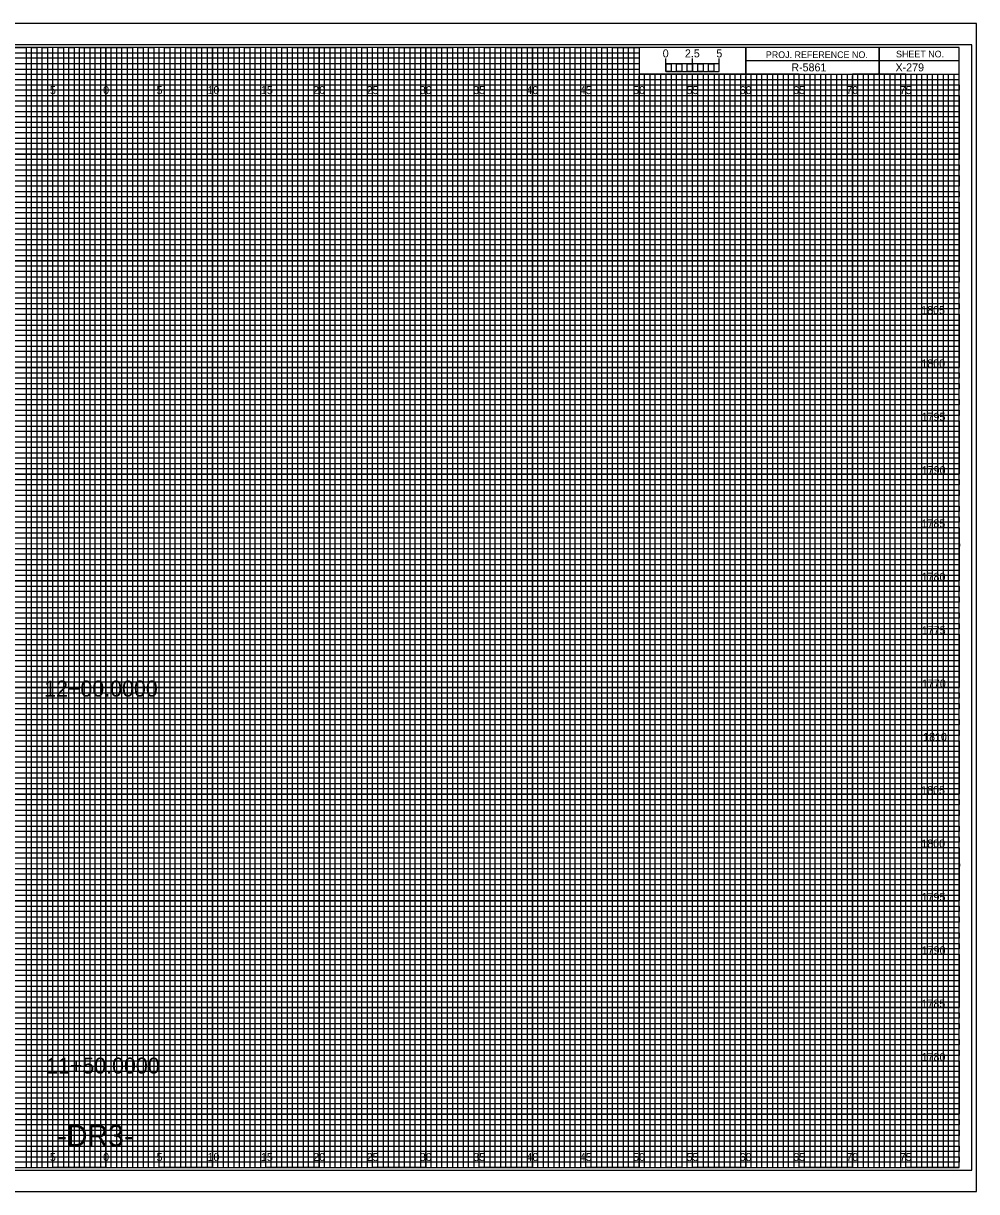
# Model space of a CAD drawing. Extents: x -7 to 162, y -2 to 217.
# Drawn here: x 72.2 to 161.7, y 107.7 to 217.2 of the extents above; entities that cross this region are included whole.
import ezdxf

# ---------------------------------------------------------------- set-up
doc = ezdxf.new("R2010")
doc.units = 0
for name, color, linetype in [('Prop Horizontal Alignment', 7, 'Continuous'), ('Prop XS Alignment Label', 7, 'Continuous'), ('Prop XS Bar Scale Labels', 7, 'Continuous'), ('Prop XS Project Number', 7, 'Continuous'), ('Prop XS Sheet Number', 7, 'Continuous'), ('Raster_Level_0', 7, 'Continuous'), ('Scratch_Level_3', 7, 'Continuous'), ('Sheet Cross Section CELL', 7, 'Continuous'), ('Sheet Cross Section Grid Major CELL', 7, 'Continuous'), ('Sheet Cross Section Grid Middle CELL', 7, 'Continuous'), ('Sheet Cross Section Grid Minor 1 CELL', 7, 'Continuous'), ('Sheet Cross Section Grid Minor 2 CELL', 7, 'Continuous'), ('Sheet Cross Section Scale CELL', 7, 'Continuous'), ('Sheet Cutting Line CELL', 7, 'Continuous'), ('Sheet DOT Grid CELL', 7, 'Continuous'), ('Sheet Plot Border Inside CELL', 7, 'Continuous'), ('Sheet Plot Border Outside CELL', 7, 'Continuous')]:
    doc.layers.add(name, color=color, linetype=linetype)

msp = doc.modelspace()

# ---------------------------------------------------------------- linework, layer by layer
at = {"layer": 'Sheet Cross Section CELL'}
for p, q in [((152.5, 215), (152.5, 212.5)), ((152.5, 212.5), (152.5, 215)), ((160, 213.75), (140, 213.75)), ((140, 213.75), (140, 212.5)), ((140, 212.5), (160, 212.5))]:
    msp.add_line(p, q, dxfattribs=at)
for points in [[(160, 215), (0, 215), (0, 110), (160, 110)], [(140, 215), (130, 215), (130, 212.52), (140, 212.52)], [(160, 215), (140, 215), (140, 212.5), (160, 212.5)]]:
    msp.add_lwpolyline(points, close=True, dxfattribs=at)
at = {"layer": 'Sheet Cross Section Grid Major CELL'}
for p, q in [((75, 215), (70, 215)), ((75, 110), (75, 215)), ((85, 215), (80, 215)), ((80, 215), (80, 110)), ((85, 110), (85, 215)), ((95, 215), (90, 215)), ((90, 215), (90, 110)), ((95, 110), (95, 215)), ((105, 215), (100, 215)), ((100, 215), (100, 110)), ((105, 110), (105, 215)), ((115, 215), (110, 215)), ((110, 215), (110, 110)), ((115, 110), (115, 215)), ((125, 215), (120, 215)), ((120, 215), (120, 110)), ((125, 110), (125, 215)), ((130, 215), (130, 110)), ((135, 110), (135, 212.5)), ((145, 212.5), (140, 212.5)), ((140, 212.5), (140, 110)), ((145, 110), (145, 212.5)), ((155, 212.5), (150, 212.5)), ((150, 212.5), (150, 110)), ((155, 110), (155, 212.5)), ((80, 110), (75, 110)), ((90, 110), (85, 110)), ((100, 110), (95, 110)), ((110, 110), (105, 110)), ((120, 110), (115, 110)), ((130, 110), (125, 110)), ((140, 110), (135, 110)), ((150, 110), (145, 110)), ((160, 110), (155, 110)), ((160, 110), (160, 110))]:
    msp.add_line(p, q, dxfattribs=at)
for points in [[(0, 210), (160, 210), (160, 205), (0, 205)], [(0, 200), (160, 200), (160, 195), (0, 195)], [(0, 190), (160, 190), (160, 185), (0, 185)], [(0, 180), (160, 180), (160, 175), (0, 175)], [(0, 170), (160, 170), (160, 165), (0, 165)], [(0, 160), (160, 160), (160, 155), (0, 155)], [(0, 150), (160, 150), (160, 145), (0, 145)], [(0, 140), (160, 140), (160, 135), (0, 135)], [(0, 130), (160, 130), (160, 125), (0, 125)], [(0, 120), (160, 120), (160, 115), (0, 115)]]:
    msp.add_lwpolyline(points, dxfattribs=at)
at = {"layer": 'Sheet Cross Section Grid Middle CELL'}
for points in [[(67.5, 215), (72.5, 215), (72.5, 110), (77.5, 110), (77.5, 215), (82.5, 215), (82.5, 110), (87.5, 110), (87.5, 215), (92.5, 215), (92.5, 110), (97.5, 110), (97.5, 215), (102.5, 215), (102.5, 110), (107.5, 110), (107.5, 215), (112.5, 215), (112.5, 110), (117.5, 110), (117.5, 215), (122.5, 215), (122.5, 110), (127.5, 110), (127.5, 215), (129.97, 215), (130, 215), (130, 212.5), (132.5, 212.5), (132.5, 110), (137.5, 110), (137.5, 212.5), (142.5, 212.5), (142.5, 110), (147.5, 110), (147.5, 212.5), (152.5, 212.5), (152.5, 110), (157.5, 110), (157.5, 212.5)], [(0, 212.5), (137.5, 212.5)], [(0, 202.5), (160, 202.5), (160, 207.5), (0, 207.5)], [(0, 192.5), (160, 192.5), (160, 197.5), (0, 197.5)], [(0, 182.5), (160, 182.5), (160, 187.5), (0, 187.5)], [(0, 172.5), (160, 172.5), (160, 177.5), (0, 177.5)], [(0, 162.5), (160, 162.5), (160, 167.5), (0, 167.5)], [(0, 152.5), (160, 152.5), (160, 157.5), (0, 157.5)], [(0, 142.5), (160, 142.5), (160, 147.5), (0, 147.5)], [(0, 132.5), (160, 132.5), (160, 137.5), (0, 137.5)], [(0, 122.5), (160, 122.5), (160, 127.5), (0, 127.5)], [(0, 112.5), (160, 112.5), (160, 117.5), (0, 117.5)]]:
    msp.add_lwpolyline(points, dxfattribs=at)
at = {"layer": 'Sheet Cross Section Grid Minor 1 CELL'}
for p, q in [((0, 214.5), (130, 214.5)), ((130, 213.99), (0, 213.99)), ((130, 214.5), (130, 213.99)), ((0, 213.5), (130, 213.5)), ((130, 212.94), (0, 212.94)), ((130, 213.5), (130, 212.94)), ((0, 212), (160, 212))]:
    msp.add_line(p, q, dxfattribs=at)
for points in [[(0, 211.5), (135, 211.5), (160, 211.5), (160, 211), (0, 211)], [(0, 210.5), (160, 210.5), (160, 209.5), (0, 209.5)], [(0, 209), (160, 209), (160, 208.5), (0, 208.49)], [(0, 208), (160, 208), (160, 207), (0, 207)], [(0, 206.5), (160, 206.5), (160, 206), (0, 206)], [(0, 205.5), (160, 205.5), (160, 204.5), (0, 204.5)], [(0, 204), (160, 204), (160, 203.5), (0, 203.5)], [(0, 203), (160, 203), (160, 202), (0, 202)], [(0, 201.5), (160, 201.5), (160, 201), (0, 201)], [(0, 200.5), (160, 200.5), (160, 199.5), (0, 199.5)], [(0, 199), (160, 199), (160, 198.5), (0, 198.5)], [(0, 198), (160, 198), (160, 196.97), (160, 196.5), (160, 196), (0, 196)], [(0, 197), (160, 197), (160, 196.5), (0, 196.5)], [(0, 195.5), (160, 195.5), (160, 194.5), (0, 194.52)], [(0, 194.52), (160, 194.5), (160, 194), (0, 194)], [(0, 193.5), (160, 193.5), (160, 193), (0, 193)], [(0, 192), (160, 192), (160, 191.5), (0, 191.5)], [(0, 191), (160, 191), (160, 190.5), (0, 190.5)], [(-0.04, 189.44), (160, 189.44), (160, 188.94), (-0.04, 188.94)], [(0, 188.5), (160, 188.5), (160, 188), (0, 188)], [(0, 187), (160, 187), (160, 186.5), (0, 186.5)], [(0, 186), (160, 186), (160, 185.5), (0, 185.5)], [(0, 184.5), (160, 184.5), (160, 184), (0, 184)], [(0, 183.5), (160, 183.5), (160, 183), (0, 183)], [(0, 182), (160, 182), (160, 181.5), (0, 181.5)], [(0, 181), (160, 181), (160, 180.5), (0, 180.5)], [(0, 179.5), (160, 179.5), (160, 178.99), (0, 179)], [(0, 178.5), (160, 178.5), (160, 178), (0, 178)], [(0, 177), (160, 177), (160, 176.5), (0, 176.5)], [(0, 176), (160, 176), (160, 175.5), (0, 175.5)], [(0, 174.5), (160, 174.5), (160, 174), (0, 174)], [(0, 173.5), (160, 173.5), (160, 173), (0, 173)], [(0, 172), (160, 172), (160, 171.5), (0, 171.5)], [(0, 171), (160, 171), (160, 170.5), (0, 170.5)], [(0, 169.5), (160, 169.5), (160, 169), (0, 169)], [(0, 168.5), (160.03, 168.46), (160, 168), (0, 168)], [(0, 167), (160, 167), (160, 166.5), (0, 166.5)], [(0, 166), (160, 166), (160, 165.5), (0, 165.5)], [(0, 164.5), (160, 164.5), (160, 164), (0, 164)], [(0, 163.5), (160, 163.5), (160, 163), (0, 163)], [(0, 162), (160, 162), (160, 161.5), (0, 161.5)], [(0, 161), (160, 161), (160, 160.5), (0, 160.5)], [(0, 159.5), (160, 159.5), (160, 159), (0, 159)], [(0, 158.5), (160, 158.5), (160, 158), (0, 158)], [(0, 157), (160, 157), (160, 156.5), (0, 156.5)], [(0, 156), (160, 156), (160, 155.5), (0, 155.5)], [(0, 154.5), (160, 154.5), (160, 154), (0, 154)], [(0, 153.5), (160, 153.5), (160, 153), (0, 153)], [(0, 152), (160, 152), (160, 151.5), (0, 151.5)], [(0, 151), (160, 151), (160, 150.5), (0, 150.5)], [(0, 149.5), (160, 149.5), (160, 148.99), (0, 149)], [(0, 148.5), (160, 148.5), (160, 148), (0, 148)], [(0, 147), (160, 147), (160, 146.5), (0, 146.5)], [(0, 146), (160, 146), (160, 145.5), (0, 145.5)], [(0, 144.5), (160, 144.5), (160, 144), (0, 144)], [(0, 143.5), (160, 143.5), (160, 143), (0, 143)], [(0, 142), (160, 142), (160, 141.5), (0, 141.5)], [(0, 141), (160, 141), (160, 140.5), (0, 140.5)], [(0, 139.5), (160, 139.5), (160, 139), (0, 139)], [(0, 138.5), (160.03, 138.46), (160, 138), (0, 138)], [(0, 137), (160, 137), (160, 136.5), (0, 136.5)], [(0, 136), (160, 136), (160, 135.5), (0, 135.5)], [(0, 134.5), (160, 134.5), (160, 134), (0, 134)], [(0, 133.5), (160, 133.5), (160, 133), (0, 133)], [(0, 132), (160, 132), (160, 131.5), (0, 131.5)], [(0, 131), (160, 131), (160, 130.5), (0, 130.5)], [(0, 129.5), (160, 129.5), (160, 129), (0, 129)], [(0, 128.5), (160, 128.5), (160, 128), (0, 128)], [(0, 127), (160, 127), (160, 126.5), (0, 126.5)], [(0, 126), (160, 126), (160, 125.5), (0, 125.5)], [(0, 124.5), (160, 124.5), (160, 124), (0, 124)], [(0, 123.5), (160, 123.5), (160, 123), (0, 123)], [(0, 122), (160, 122), (160, 121.5), (0, 121.5)], [(0, 121), (160, 121), (160, 120.5), (0, 120.5)], [(0, 119.5), (160, 119.5), (160, 119), (0, 119)], [(0, 118.5), (160, 118.5), (160, 118), (0, 118)], [(0, 117), (160, 117), (160, 116.5), (0, 116.5)], [(0, 116), (160, 116), (160, 115.5), (0, 115.5)], [(0, 114.5), (160, 114.5), (160, 114), (0, 114)], [(0, 113.5), (160, 113.5), (160, 113), (0, 113)], [(0, 112), (160, 112), (160, 111.5), (0, 111.5)], [(0, 111), (160, 111), (160, 110.5), (0, 110.5)]]:
    msp.add_lwpolyline(points, dxfattribs=at)
at = {"layer": 'Sheet Cross Section Grid Minor 2 CELL'}
for p, q in [((133.5, 212.5), (133, 212.5)), ((133, 212.5), (133, 110)), ((133.5, 110), (133.5, 212.5)), ((134.5, 212.5), (134, 212.5)), ((134, 212.5), (134, 110)), ((134.5, 110), (134.5, 212.5)), ((133, 110), (132.5, 110)), ((134, 110), (133.5, 110))]:
    msp.add_line(p, q, dxfattribs=at)
for points in [[(72.5, 110), (73, 110), (73, 215), (73.5, 215), (73.5, 110)], [(73.5, 110), (74, 110), (74, 215), (74.5, 215), (74.5, 110)], [(75, 110), (75.5, 110), (75.5, 215), (76, 215), (76, 110)], [(76, 110), (76.5, 110), (76.5, 215), (77, 215), (77, 110)], [(77.5, 110), (78, 110), (78, 215), (78.5, 215), (78.5, 110)], [(78.5, 110), (79, 110), (79, 215), (79.5, 215), (79.5, 110)], [(80, 110), (80.5, 110), (80.5, 215), (81, 215), (81, 110)], [(81, 110), (81.5, 110), (81.5, 215), (82, 215), (82, 110)], [(82.5, 110), (83, 110), (83, 215), (83.5, 215), (83.5, 110)], [(83.5, 110), (84, 110), (84, 215), (84.5, 215), (84.5, 110)], [(85, 110), (85.5, 110), (85.5, 215), (86, 215), (86, 110)], [(86, 110), (86.5, 110), (86.5, 215), (87, 215), (87, 110)], [(87.5, 110), (88, 110), (88, 215), (88.5, 215), (88.5, 110)], [(88.5, 110), (89, 110), (89, 215), (89.5, 215), (89.5, 110)], [(90, 110), (90.5, 110), (90.5, 215), (91, 215), (91, 110)], [(91, 110), (91.5, 110), (91.5, 215), (92, 215), (92, 110)], [(92.5, 110), (93, 110), (93, 215), (93.5, 215), (93.5, 110)], [(93.5, 110), (94, 110), (94, 215), (94.5, 215), (94.5, 110)], [(95, 110), (95.5, 110), (95.5, 215), (96, 215), (96, 110)], [(96, 110), (96.5, 110), (96.5, 215), (97, 215), (97, 110)], [(97.5, 110), (98, 110), (98, 215), (98.5, 215), (98.5, 110)], [(98.5, 110), (99, 110), (99, 215), (99.5, 215), (99.5, 110)], [(100, 110), (100.5, 110), (100.5, 215), (101, 215), (101, 110)], [(101, 110), (101.5, 110), (101.5, 215), (102, 215), (102, 110)], [(102.5, 110), (103, 110), (103, 215), (103.5, 215), (103.5, 110)], [(103.5, 110), (104, 110), (104, 215), (104.5, 215), (104.5, 110)], [(105, 110), (105.5, 110), (105.5, 215), (106, 215), (106, 110)], [(106, 110), (106.5, 110), (106.5, 215), (107, 215), (107, 110)], [(107.5, 110), (108, 110), (108, 215), (108.5, 215), (108.5, 110)], [(108.5, 110), (109, 110), (109, 215), (109.5, 215), (109.5, 110)], [(110, 110), (110.5, 110), (110.5, 215), (111, 215), (111, 110)], [(111, 110), (111.5, 110), (111.5, 215), (112, 215), (112, 110)], [(112.5, 110), (113, 110), (113, 215), (113.5, 215), (113.5, 110)], [(113.5, 110), (114, 110), (114, 215), (114.5, 215), (114.5, 110)], [(115, 110), (115.5, 110), (115.5, 215), (116, 215), (116, 110)], [(116, 110), (116.5, 110), (116.5, 215), (117, 215), (117, 110)], [(117.5, 110), (118, 110), (118, 215), (118.5, 215), (118.5, 110)], [(118.5, 110), (119, 110), (119, 215), (119.5, 215), (119.5, 110)], [(120, 110), (120.5, 110), (120.5, 215), (121, 215), (121, 110)], [(121, 110), (121.5, 110), (121.5, 215), (122, 215), (122, 110)], [(122.5, 110), (123, 110), (123, 215), (123.5, 215), (123.5, 110)], [(123.5, 110), (124, 110), (124, 215), (124.5, 215), (124.5, 110)], [(125, 110), (125.5, 110), (125.5, 215), (126, 215), (126, 110)], [(126, 110), (126.5, 110), (126.5, 215), (127, 215), (127, 110)], [(127.5, 110), (128, 110), (128, 215), (128.5, 215), (128.5, 110)], [(128.5, 110), (129, 110), (129, 215), (129.5, 215), (129.5, 110)], [(130, 110), (130.5, 110), (130.5, 212.5), (131.01, 212.5), (131.01, 110)], [(131, 110), (131.5, 110), (131.5, 212.5), (132, 212.5), (132, 110)], [(135, 110), (135.49, 110), (135.49, 212.5), (136, 212.5), (136, 110)], [(136, 110), (136.5, 110), (136.5, 212.5), (137.03, 212.5), (137.03, 110)], [(137.5, 110), (138, 110), (138, 212.5), (138.5, 212.5), (138.5, 110)], [(138.5, 110), (139, 110), (139, 212.5), (139.5, 212.5), (139.5, 110)], [(140, 110), (140.5, 110), (140.5, 212.5), (141, 212.5), (141, 110)], [(141, 110), (141.5, 110), (141.5, 212.5), (142, 212.5), (142, 110)], [(142.5, 110), (143, 110), (143, 212.5), (143.5, 212.5), (143.5, 110)], [(143.5, 110), (144, 110), (144, 212.5), (144.5, 212.5), (144.5, 110)], [(145, 110), (145.5, 110), (145.5, 212.5), (146, 212.5), (146, 110)], [(146, 110), (146.5, 110), (146.5, 212.5), (147, 212.5), (147, 110)], [(147.5, 110), (148, 110), (148, 212.5), (148.5, 212.5), (148.5, 110)], [(148.5, 110), (149, 110), (149, 212.5), (149.5, 212.5), (149.5, 110)], [(150, 110), (150.5, 110), (150.5, 212.5), (151, 212.5), (151, 110)], [(151, 110), (151.5, 110), (151.5, 212.5), (152, 212.5), (152, 110)], [(152.5, 110), (153, 110), (153, 212.5), (153.5, 212.5), (153.5, 110)], [(153.5, 110), (154, 110), (154, 212.5), (154.5, 212.5), (154.5, 110)], [(155, 110), (155.5, 110), (155.5, 212.5), (156, 212.5), (156, 110)], [(156, 110), (156.5, 110), (156.5, 212.5), (157, 212.5), (157, 110)], [(157.5, 110), (158, 110), (158, 212.5), (158.5, 212.5), (158.5, 110)], [(158.5, 110), (159, 110), (159, 212.5), (159.5, 212.5), (159.5, 110)]]:
    msp.add_lwpolyline(points, dxfattribs=at)
at = {"layer": 'Sheet Cross Section Scale CELL'}
for p, q in [((132.5, 212.75), (132.5, 213.95)), ((132.5, 213.45), (132.5, 213.95)), ((135, 212.75), (135, 213.95)), ((137.5, 212.75), (137.5, 213.95)), ((137.5, 213.45), (137.5, 213.95))]:
    msp.add_line(p, q, dxfattribs=at)
for points in [[(137.5, 213.45), (132.5, 213.45), (132.5, 212.75), (137.5, 212.75)], [(132.5, 213.45), (133, 213.45), (133, 212.75), (132.5, 212.75)], [(133.5, 213.45), (134, 213.45), (134, 212.75), (133.5, 212.75)], [(134.5, 213.45), (135, 213.45), (135, 212.75), (134.5, 212.75)], [(135.5, 213.45), (136, 213.45), (136, 212.75), (135.5, 212.75)], [(136.5, 213.45), (137, 213.45), (137, 212.75), (136.5, 212.75)]]:
    msp.add_lwpolyline(points, close=True, dxfattribs=at)
at = {"layer": 'Sheet Cutting Line CELL'}
for p, q in [((161.65, 217.25), (-6.7, 217.25)), ((-6.7, 107.75), (161.65, 107.75))]:
    msp.add_line(p, q, dxfattribs=at)
at = {"layer": 'Sheet DOT Grid CELL'}
for p, q in [((75, 110), (75, 215)), ((80, 110), (80, 215)), ((85, 110), (85, 215)), ((90, 110), (90, 215)), ((95, 110), (95, 215)), ((100, 110), (100, 215)), ((105, 110), (105, 215)), ((110, 110), (110, 215)), ((115, 110), (115, 215)), ((120, 110), (120, 215)), ((125, 110), (125, 215)), ((130, 110), (130, 212.34)), ((135, 110), (135, 212.34)), ((140, 110), (140, 212.34)), ((145, 110), (145, 212.34)), ((150, 110), (150, 212.34)), ((155, 110), (155, 212.34)), ((0, 210), (160, 210)), ((0, 205), (160, 205)), ((0, 200), (160, 200)), ((0, 195), (160, 195)), ((0, 190), (160, 190)), ((0, 185), (160, 185)), ((0, 180), (160, 180)), ((0, 175), (160, 175)), ((0, 170), (160, 170)), ((0, 165), (160, 165)), ((0, 160), (160, 160)), ((0, 155), (160, 155)), ((0, 150), (160, 150)), ((0, 145), (160, 145)), ((0, 140), (160, 140)), ((0, 135), (160, 135)), ((0, 130), (160, 130)), ((0, 125), (160, 125)), ((0, 120), (160, 120)), ((0, 115), (160, 115))]:
    msp.add_line(p, q, dxfattribs=at)
at = {"layer": 'Sheet Plot Border Inside CELL'}
msp.add_lwpolyline([(-5.4, 109.75), (161.2, 109.75), (161.2, 215.25), (-5.4, 215.25)], close=True, dxfattribs=at)
at = {"layer": 'Sheet Plot Border Outside CELL'}
msp.add_lwpolyline([(-6.7, 107.75), (161.65, 107.75), (161.65, 217.25), (-6.7, 217.25)], close=True, dxfattribs=at)

# ---------------------------------------------------------------- texts
at = {"layer": 'Prop Horizontal Alignment'}
for s, p in [('12+00.0000', (74.2, 154.15)), ('11+50.0000', (74.38, 118.81))]:
    msp.add_text(s, height=1.5, dxfattribs=at).set_placement(p)
at = {"layer": 'Prop XS Alignment Label'}
msp.add_text('-DR3-', height=2, dxfattribs=at).set_placement((75.44, 112))
at = {"layer": 'Prop XS Bar Scale Labels'}
for s, p in [('2.5', (134.29, 214.06)), ('5', (137.24, 214.06))]:
    msp.add_text(s, height=0.75, dxfattribs=at).set_placement(p)
at = {"layer": 'Prop XS Project Number'}
msp.add_text('R-5861', height=0.75, dxfattribs=at).set_placement((144.27, 212.75))
at = {"layer": 'Prop XS Sheet Number'}
msp.add_text('X-279', height=0.75, dxfattribs=at).set_placement((154.04, 212.75))
at = {"layer": 'Raster_Level_0'}
for s, p in [('5', (74.74, 210.62)), ('0', (79.73, 210.62)), ('0', (79.73, 210.62)), ('5', (84.74, 210.62)), ('10', (89.52, 210.62)), ('15', (94.53, 210.62)), ('20', (99.43, 210.62)), ('25', (104.44, 210.62)), ('30', (109.43, 210.62)), ('35', (114.44, 210.62)), ('40', (119.43, 210.62)), ('45', (124.44, 210.62)), ('50', (129.43, 210.62)), ('55', (134.44, 210.62)), ('60', (139.43, 210.62)), ('65', (144.44, 210.62)), ('70', (149.43, 210.62)), ('75', (154.44, 210.62)), ('5', (74.74, 110.62)), ('0', (79.73, 110.62)), ('0', (79.73, 110.62)), ('5', (84.74, 110.62)), ('10', (89.52, 110.62)), ('15', (94.53, 110.62)), ('20', (99.43, 110.62)), ('25', (104.44, 110.62)), ('30', (109.43, 110.62)), ('35', (114.44, 110.62)), ('40', (119.43, 110.62)), ('45', (124.44, 110.62)), ('50', (129.43, 110.62)), ('55', (134.44, 110.62)), ('60', (139.43, 110.62)), ('65', (144.44, 110.62)), ('70', (149.43, 110.62)), ('75', (154.44, 110.62))]:
    msp.add_text(s, height=0.75, dxfattribs=at).set_placement(p)
at = {"layer": 'Scratch_Level_3'}
for s, p in [('1805', (156.45, 190)), ('1800', (156.46, 185)), ('1795', (156.49, 180)), ('1790', (156.5, 175)), ('1785', (156.48, 170)), ('1780', (156.49, 165)), ('1775', (156.51, 160)), ('1770', (156.52, 155)), ('1810', (156.63, 150)), ('1805', (156.45, 145)), ('1800', (156.46, 140)), ('1795', (156.49, 135)), ('1790', (156.5, 130)), ('1785', (156.48, 125)), ('1780', (156.49, 120))]:
    msp.add_text(s, height=0.75, dxfattribs=at).set_placement(p)
at = {"layer": 'Sheet Cross Section CELL'}
for s, p in [('PROJ. REFERENCE NO.', (141.88, 214)), ('SHEET NO.', (154.09, 214.06))]:
    msp.add_text(s, height=0.625, dxfattribs=at).set_placement(p)
at = {"layer": 'Sheet Cross Section Scale CELL'}
msp.add_text('0', height=0.75, dxfattribs=at).set_placement((132.21, 214.06))

doc.saveas('drawing.dxf')
